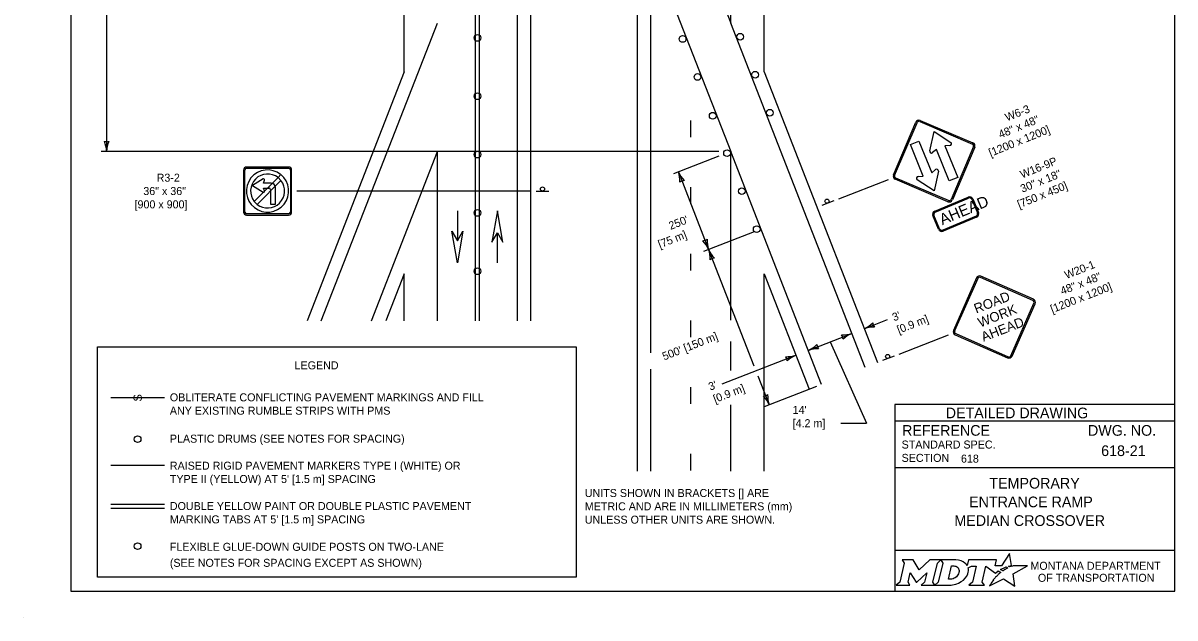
# Model space of a CAD drawing. Extents: x 49991.4 to 50021, y 49987.6 to 50011.4.
# Drawn here: x 49999.98 to 50008.61, y 49999.86 to 50004.32 of the extents above; entities that cross this region are included whole.
import ezdxf

# ---------------------------------------------------------------- set-up
doc = ezdxf.new("R2010")
doc.units = 0
for name, color, linetype in [('Level 1', 7, 'Continuous'), ('Level 2', 7, 'Continuous'), ('Level 3', 7, 'Continuous')]:
    doc.layers.add(name, color=color, linetype=linetype)

msp = doc.modelspace()

# ---------------------------------------------------------------- linework, layer by layer
at = {"layer": 'Level 1'}
for p, q in [((50005.2837, 50004.324), (50005.2837, 50010.8774)), ((50005.5337, 50003.9574), (50005.5337, 50010.8774)), ((50003.3688, 50002.0911), (50003.3688, 50010.5919)), ((50002.8337, 50003.9575), (50002.8337, 50010.5493)), ((50003.3988, 50002.0911), (50003.3988, 50010.5067)), ((50003.9712, 50007.6888), (50005.2838, 50004.3238)), ((50003.7838, 50002.0911), (50003.7838, 50006.931)), ((50003.6838, 50002.0911), (50003.6838, 50006.593)), ((50004.1009, 50006.393), (50005.2837, 50003.3608)), ((50004.5838, 50000.9624), (50004.5838, 50004.8798)), ((50004.6838, 50001.8518), (50004.6838, 50004.8987)), ((50002.2131, 50002.0911), (50003.0837, 50004.324)), ((50006.2908, 50001.741), (50005.2837, 50004.324)), ((50002.8337, 50003.9575), (50002.1063, 50002.0911)), ((50005.5337, 50003.9575), (50006.3835, 50001.7771)), ((50004.9838, 50003.469), (50004.9838, 50003.594)), ((50006.5034, 50003.1847), (50006.6713, 50003.5805)), ((50006.5127, 50003.1809), (50006.6806, 50003.5767)), ((50006.7003, 50003.5847), (50007.096, 50003.4168)), ((50006.7041, 50003.5938), (50007.1001, 50003.426)), ((50006.7761, 50003.3651), (50006.8088, 50003.5116)), ((50006.8088, 50003.5116), (50006.9339, 50003.4289)), ((50006.6315, 50003.4123), (50006.6945, 50003.4378)), ((50006.7273, 50003.1753), (50006.6315, 50003.4123)), ((50006.6945, 50003.4378), (50006.7903, 50003.2008)), ((50006.9277, 50003.4052), (50006.8896, 50003.4023)), ((50006.8896, 50003.4023), (50006.9853, 50003.1656)), ((50007.104, 50003.3971), (50006.9362, 50003.0011)), ((50002.5887, 50002.0911), (50003.0837, 50003.3608)), ((50003.0837, 50002.0911), (50003.0837, 50003.3608)), ((50005.9648, 50001.6138), (50005.2837, 50003.3608)), ((50005.2837, 50002.096), (50005.2837, 50003.3607)), ((50006.8266, 50003.3768), (50006.7972, 50003.3525)), ((50006.9223, 50003.1401), (50006.8266, 50003.3768)), ((50007.1134, 50003.3931), (50006.9453, 50002.9973)), ((50001.9681, 50003.2442), (50001.6531, 50003.2442)), ((50001.6531, 50003.2349), (50001.9681, 50003.2349)), ((50006.7903, 50003.2008), (50006.8195, 50003.2256)), ((50001.6307, 50003.2217), (50001.6307, 50002.9067)), ((50001.6401, 50002.9067), (50001.6401, 50003.2217)), ((50001.7763, 50003.1547), (50001.6981, 50003.1055)), ((50001.7105, 50002.9853), (50001.8895, 50003.1644)), ((50001.9107, 50003.1432), (50001.7317, 50002.9641)), ((50001.7763, 50003.1547), (50001.7763, 50003.1547)), ((50001.7803, 50003.1242), (50001.7873, 50003.1462)), ((50001.8891, 50003.1648), (50001.9085, 50003.1881)), ((50001.9091, 50003.1877), (50001.8895, 50003.1644)), ((50001.8895, 50003.1644), (50001.9107, 50003.1432)), ((50001.8895, 50003.1644), (50001.9107, 50003.1432)), ((50001.9907, 50003.2217), (50001.9813, 50003.2217)), ((50001.9813, 50003.2217), (50001.9907, 50003.2217)), ((50001.9907, 50003.2216), (50001.9813, 50003.2216)), ((50001.9813, 50003.2216), (50001.9813, 50002.9067)), ((50001.9907, 50002.9067), (50001.9907, 50003.2216)), ((50006.9125, 50002.984), (50006.5167, 50003.1519)), ((50006.9165, 50002.9932), (50006.5207, 50003.1613)), ((50006.808, 50003.0663), (50006.6826, 50003.1491)), ((50006.689, 50003.1728), (50006.7273, 50003.1753)), ((50006.8406, 50003.213), (50006.808, 50003.0663)), ((50006.9853, 50003.1656), (50006.9223, 50003.1401)), ((50001.6981, 50003.1055), (50001.7763, 50003.0562)), ((50001.8367, 50003.1242), (50001.7803, 50003.1242)), ((50001.7873, 50003.0648), (50001.7803, 50003.0867)), ((50001.7803, 50003.0867), (50001.8205, 50003.0867)), ((50001.8331, 50003.074), (50001.8331, 50002.9667)), ((50001.8707, 50002.9667), (50001.8707, 50003.0902)), ((50003.8238, 50003.0642), (50003.9198, 50003.0642)), ((50004.9838, 50002.969), (50004.9838, 50003.094)), ((50001.7317, 50002.9641), (50001.7105, 50002.9853)), ((50001.7317, 50002.9641), (50001.7105, 50002.9853)), ((50001.8331, 50002.9667), (50001.8707, 50002.9667)), ((50006.0562, 50002.9914), (50005.9667, 50002.9566)), ((50006.8131, 50002.9142), (50007.0642, 50003.0193)), ((50006.8163, 50002.9064), (50007.0674, 50003.0116)), ((50007.0905, 50003.0021), (50007.1333, 50002.8998)), ((50007.0983, 50003.0053), (50007.1411, 50002.9031)), ((50001.9681, 50002.8936), (50001.6531, 50002.8936)), ((50001.6531, 50002.8842), (50001.9681, 50002.8842)), ((50003.2337, 50002.9159), (50003.2337, 50002.6901)), ((50003.2339, 50002.9159), (50003.2339, 50002.6901)), ((50006.842, 50002.7778), (50006.7991, 50002.8801)), ((50006.8497, 50002.7811), (50006.8069, 50002.8834)), ((50006.8131, 50002.9142), (50006.8131, 50002.9142)), ((50006.8163, 50002.9064), (50006.8163, 50002.9064)), ((50007.1239, 50002.8767), (50006.8728, 50002.7716)), ((50007.1271, 50002.869), (50006.876, 50002.7639)), ((50003.5336, 50002.5259), (50003.5336, 50002.7517)), ((50003.5338, 50002.5259), (50003.5338, 50002.7517)), ((50004.9838, 50002.469), (50004.9838, 50002.594)), ((50002.8337, 50002.4442), (50002.6961, 50002.0911)), ((50002.8337, 50002.0911), (50002.8337, 50002.4442)), ((50005.5337, 50002.4442), (50005.8715, 50001.5774)), ((50005.5337, 50001.5963), (50005.5337, 50002.4442)), ((50007.1266, 50002.4121), (50006.9536, 50002.0185)), ((50007.1358, 50002.4084), (50006.9626, 50002.0147)), ((50007.5492, 50002.2428), (50007.1556, 50002.4162)), ((50007.5531, 50002.252), (50007.1597, 50002.4251)), ((50007.3839, 50001.8294), (50007.5568, 50002.223)), ((50007.3929, 50001.8255), (50007.566, 50002.219)), ((50004.9838, 50001.969), (50004.9838, 50002.094)), ((50005.2837, 50001.7181), (50005.2837, 50001.9348)), ((50006.9663, 50001.9858), (50007.3599, 50001.8125)), ((50006.9704, 50001.9949), (50007.3639, 50001.8217)), ((50000.5356, 50000.1675), (50000.5356, 50001.8961)), ((50000.5356, 50001.8961), (50004.124, 50001.8961)), ((50004.124, 50001.8961), (50004.124, 50000.1675)), ((50006.5099, 50001.8268), (50006.4204, 50001.7921)), ((50004.6838, 50000.9624), (50004.6838, 50001.7274)), ((50004.9838, 50001.469), (50004.9838, 50001.594)), ((50005.5337, 50000.9624), (50005.5337, 50001.5963)), ((50001.0367, 50001.5139), (50000.6356, 50001.5139)), ((50005.2837, 50000.9624), (50005.2837, 50001.4605)), ((50004.9838, 50000.969), (50004.9838, 50001.094)), ((50001.0367, 50001.0057), (50000.6356, 50001.0057)), ((50000.6356, 50000.7154), (50001.0367, 50000.7154)), ((50000.6356, 50000.6854), (50001.0367, 50000.6854)), ((50004.124, 50000.1675), (50000.5356, 50000.1675)), ((49999.9766, 49999.8624), (49999.9766, 49999.8624))]:
    msp.add_line(p, q, dxfattribs=at)
for points in [[(50008.6146, 50011.2628), (50000.3356, 50011.2628), (50000.3356, 50000.0624), (50008.6146, 50000.0624)], [(50003.5756, 50002.6795), (50003.5338, 50002.9159), (50003.492, 50002.6795), (50003.5338, 50002.7515)], [(50003.2757, 50002.7623), (50003.2339, 50002.5259), (50003.1921, 50002.7623), (50003.2339, 50002.6903)]]:
    msp.add_lwpolyline(points, close=True, dxfattribs=at)
for centre, radius in [((50003.3838, 50004.2123), 0.025), ((50004.9229, 50004.2044), 0.025), ((50005.3546, 50004.2214), 0.025), ((50005.034, 50003.9194), 0.025), ((50005.4658, 50003.9364), 0.025), ((50003.3838, 50003.7748), 0.025), ((50005.577, 50003.6514), 0.025), ((50005.148, 50003.629), 0.025), ((50003.3838, 50003.3373), 0.025), ((50005.2556, 50003.3479), 0.025), ((50003.8717, 50003.0794), 0.0152), ((50005.3668, 50003.0629), 0.025), ((50006.0055, 50002.9882), 0.0152), ((50003.3838, 50002.8998), 0.025), ((50005.478, 50002.7779), 0.025), ((50003.3838, 50002.4623), 0.025), ((50006.4596, 50001.8236), 0.0152), ((50000.836, 50001.2037), 0.025), ((50000.8361, 50000.401), 0.025)]:
    msp.add_circle(centre, radius, dxfattribs=at)
for centre, radius, start, end in [((50006.6942, 50003.5707), 0.025, 67.01358, 157.01358), ((50006.6942, 50003.5707), 0.015, 67.01358, 157.01358), ((50006.9266, 50003.4179), 0.0129, 274.05539, 345.29114), ((50006.9266, 50003.4179), 0.0129, 345.29419, 56.53298), ((50007.0901, 50003.4028), 0.015, 337.01358, 67.01358), ((50007.0901, 50003.4028), 0.025, 337.01358, 67.01358), ((50006.7886, 50003.3621), 0.0129, 167.59853, 238.72992), ((50006.7886, 50003.3621), 0.0129, 238.73297, 309.97176), ((50001.6531, 50003.2218), 0.0225, 90, 180), ((50001.6531, 50003.2218), 0.0131, 90, 180), ((50001.9681, 50003.2218), 0.0225, 0, 90), ((50001.9681, 50003.2218), 0.0131, 0, 90), ((50006.8277, 50003.2156), 0.0129, 58.73297, 129.97176), ((50006.8277, 50003.2156), 0.0129, 347.59853, 58.72992), ((50001.8101, 50003.0639), 0.1585, 51.65928, 51.42697), ((50001.8106, 50003.0643), 0.1275, 52.04534, 218.24287), ((50001.8106, 50003.0643), 0.1275, 135.58365, 135.71312), ((50001.8106, 50003.0643), 0.1275, 231.75713, 38.2435), ((50001.7801, 50003.1485), 0.00742, 342.38136, 122.24299), ((50006.5263, 50003.1749), 0.025, 157.01334, 247.01358), ((50006.5263, 50003.1749), 0.015, 157.01334, 247.01358), ((50006.6897, 50003.1598), 0.0129, 165.29419, 236.53298), ((50006.6897, 50003.1598), 0.0129, 94.05539, 165.29114), ((50001.7801, 50003.0626), 0.00742, 237.75616, 17.61961), ((50001.8204, 50003.0741), 0.0128, 0, 90), ((50001.8366, 50003.0903), 0.034, 0, 90), ((50001.8106, 50003.0643), 0.1275, 319.12855, 319.14364), ((50006.9221, 50003.007), 0.025, 247.01401, 337.01358), ((50006.9221, 50003.007), 0.015, 247.01401, 337.01358), ((50007.0742, 50002.9953), 0.026, 22.71919, 112.71919), ((50007.0742, 50002.9953), 0.0176, 22.71919, 112.71919), ((50001.6531, 50002.9068), 0.0225, 180, 270), ((50001.6531, 50002.9068), 0.0131, 180, 270), ((50001.9681, 50002.9068), 0.0225, 270, 0), ((50001.9681, 50002.9068), 0.0131, 270, 0), ((50006.8232, 50002.8902), 0.026, 112.71919, 202.71919), ((50006.8232, 50002.8902), 0.0176, 112.71919, 202.71919), ((50007.1171, 50002.893), 0.0176, 292.71919, 22.71919), ((50007.1171, 50002.893), 0.026, 292.71919, 22.71919), ((50006.866, 50002.7879), 0.026, 202.71919, 292.71919), ((50006.866, 50002.7879), 0.0176, 202.71919, 292.71919), ((50007.1497, 50002.402), 0.025, 66.25, 156.25), ((50007.1497, 50002.402), 0.015, 66.25, 156.25), ((50007.5433, 50002.2289), 0.015, 336.25, 66.25024), ((50007.5433, 50002.2289), 0.025, 336.25, 66.25024), ((50006.9765, 50002.0085), 0.025, 156.25, 246.25), ((50006.9765, 50002.0085), 0.015, 156.25, 246.25), ((50007.3701, 50001.8353), 0.025, 246.25, 336.24957), ((50007.3701, 50001.8353), 0.015, 246.25, 336.24957)]:
    msp.add_arc(centre, radius, start, end, dxfattribs=at)
at = {"layer": 'Level 2'}
for p, q in [((50008.6146, 50001.4624), (50006.5146, 50001.4624)), ((50006.5146, 50001.4624), (50006.5146, 50000.0624)), ((50008.6146, 50001.3374), (50006.5146, 50001.3374)), ((50008.2507, 50001.1223), (50008.2507, 50001.1223)), ((50008.6146, 50000.9874), (50006.5146, 50000.9874)), ((50007.0089, 50001.0629), (50007.0089, 50001.0629)), ((50007.5646, 50000.7383), (50007.5646, 50000.7383)), ((50008.6146, 50000.3693), (50006.5146, 50000.3693))]:
    msp.add_line(p, q, dxfattribs=at)
for points in [[(50006.5701, 50000.2974), (50006.5842, 50000.274), (50006.5507, 50000.1307), (50006.525, 50000.1082), (50006.6266, 50000.1082), (50006.6131, 50000.131), (50006.6293, 50000.2011), (50006.673, 50000.1321), (50006.6783, 50000.1321), (50006.7534, 50000.2016), (50006.737, 50000.1305), (50006.7123, 50000.1085), (50006.8139, 50000.1085), (50006.8001, 50000.1318), (50006.8333, 50000.2742)], [(50006.8333, 50000.2742), (50006.8586, 50000.2974), (50006.7762, 50000.2974), (50006.6966, 50000.2244), (50006.6521, 50000.2971), (50006.5701, 50000.2974)], [(50006.9722, 50000.2974), (50006.8586, 50000.2974), (50006.8733, 50000.2745), (50006.8394, 50000.1307), (50006.8139, 50000.1085), (50006.9245, 50000.1085)], [(50007.3771, 50000.2447), (50007.3668, 50000.2503), (50007.3784, 50000.2531), (50007.39, 50000.2551), (50007.3726, 50000.3452), (50007.3131, 50000.2539), (50007.2658, 50000.2532), (50007.2761, 50000.2973), (50007.0669, 50000.2974), (50007.0568, 50000.2549), (50007.051, 50000.2632)], [(50006.9962, 50000.2107), (50006.995, 50000.2026), (50006.9918, 50000.1933), (50006.9876, 50000.1851), (50006.982, 50000.1776), (50006.9755, 50000.1707), (50006.9676, 50000.1644), (50006.9593, 50000.1597), (50006.9502, 50000.1558), (50006.9411, 50000.1535), (50006.9319, 50000.1526), (50006.916, 50000.1526), (50006.9396, 50000.2526), (50006.9556, 50000.2526), (50006.9632, 50000.252), (50006.9708, 50000.2501), (50006.9774, 50000.2471), (50006.9835, 50000.2429), (50006.9883, 50000.2379), (50006.992, 50000.2319), (50006.9947, 50000.2257), (50006.9963, 50000.2183), (50006.9963, 50000.2153), (50006.9962, 50000.2107)], [(50007.0636, 50000.2383), (50007.0882, 50000.2514), (50007.1251, 50000.2514), (50007.0965, 50000.1309), (50007.069, 50000.1082), (50007.1852, 50000.1082), (50007.1682, 50000.1311), (50007.1964, 50000.2513), (50007.2677, 50000.1996), (50007.2888, 50000.2147), (50007.3085, 50000.2038)], [(50007.2527, 50000.1479), (50007.2374, 50000.1235), (50007.2327, 50000.116), (50007.2269, 50000.1074), (50007.2246, 50000.1031), (50007.3299, 50000.1562), (50007.4138, 50000.1011), (50007.4007, 50000.1938), (50007.5076, 50000.2522), (50007.4583, 50000.253), (50007.4282, 50000.2534), (50007.4074, 50000.2537), (50007.4006, 50000.2522), (50007.3957, 50000.251), (50007.3873, 50000.2487), (50007.3771, 50000.2447)], [(50007.3267, 50000.2171), (50007.3243, 50000.2154), (50007.306, 50000.225), (50007.3163, 50000.2307), (50007.3204, 50000.2329), (50007.329, 50000.2369), (50007.3347, 50000.2395), (50007.3426, 50000.2425), (50007.3499, 50000.2452), (50007.3617, 50000.2378), (50007.3577, 50000.2357), (50007.3531, 50000.2332), (50007.3489, 50000.231), (50007.3439, 50000.2281), (50007.342, 50000.227), (50007.3393, 50000.2254), (50007.3368, 50000.224), (50007.3345, 50000.2224), (50007.3319, 50000.2206), (50007.3292, 50000.2188), (50007.3267, 50000.2171)], [(50006.9702, 50000.1158), (50006.9786, 50000.1184), (50006.9916, 50000.1238), (50007.012, 50000.1348)], [(50007.2666, 50000.164), (50007.2666, 50000.164)]]:
    msp.add_lwpolyline(points, dxfattribs=at)
for centre, radius, start, end in [((50006.9953, 50000.219), 0.0709, 339.53292, 15.85821), ((50006.9513, 50000.2363), 0.1183, 300.91025, 339.13831)]:
    msp.add_arc(centre, radius, start, end, dxfattribs=at)
for centre, major_axis, ratio, start_param, end_param in [((50006.9701, 50000.25), (0.0834, -0.0037), 0.568097, 0.61298, 1.570796), ((50007.0257, 50000.2573), (0.0361, -0.0295), 0.469099, 1.225588, 1.570796), ((50007.2974, 50000.1941), (-0.0112, -0.0097), 0.021651, 3.157348, 6.283185), ((50006.9248, 50000.2568), (0, 0.1484), 0.987302, 3.139398, 3.456847), ((50007.2597, 50000.1559), (-0.00694, -0.00806), 0.008222, 0, 3.137361), ((50007.2764, 50000.1742), (-0.0098, -0.0102), 0.016458, 3.141593, 6.279097)]:
    msp.add_ellipse(centre, major_axis=major_axis, ratio=ratio, start_param=start_param, end_param=end_param, dxfattribs=at)
at = {"layer": 'Level 3'}
for p, q in [((50000.6034, 50007.4623), (50000.6034, 50003.3608)), ((50005.1943, 50003.3608), (50000.5634, 50003.3608)), ((50005.1945, 50003.3259), (50004.8534, 50003.1929)), ((50004.8907, 50003.2075), (50005.1178, 50002.6252)), ((50006.0934, 50003.0061), (50006.4659, 50003.1509)), ((50003.7838, 50003.0642), (50002.0307, 50003.0642)), ((50005.4588, 50002.7593), (50005.0802, 50002.6116)), ((50005.1178, 50002.6252), (50005.4579, 50001.7535)), ((50006.2842, 50002.0319), (50006.4596, 50002.1001)), ((50005.8653, 50001.869), (50006.1915, 50001.9958)), ((50006.0284, 50001.9324), (50006.3019, 50001.3228)), ((50006.5471, 50001.8414), (50006.916, 50001.9848)), ((50005.2199, 50001.618), (50005.772, 50001.8327)), ((50005.4869, 50001.6789), (50005.5721, 50001.4606)), ((50005.9275, 50001.5993), (50005.5348, 50001.4461)), ((50006.1089, 50001.3228), (50006.3019, 50001.3228))]:
    msp.add_line(p, q, dxfattribs=at)
for centre, radius, start, end in [((50000.6034, 50003.489), 0.0548, 252.13882, 287.86118), ((50000.3707, 50003.3493), 0.233, 2.82731, 22.07716), ((50000.8256, 50003.3516), 0.2223, 157.45601, 177.63952), ((50004.6804, 50003.1353), 0.2223, 358.76551, 18.94902), ((50005.1033, 50003.3027), 0.233, 204.13681, 223.38666), ((50004.9373, 50003.088), 0.0548, 93.44832, 129.17068), ((50005.0709, 50002.7456), 0.0548, 273.44832, 309.17068), ((50004.9049, 50002.5308), 0.233, 24.13681, 43.38666), ((50005.3278, 50002.6983), 0.2223, 178.76551, 198.94902), ((50004.9072, 50002.5539), 0.2223, 358.76551, 18.94902), ((50005.3301, 50002.7214), 0.233, 204.13681, 223.38666), ((50005.1641, 50002.5067), 0.0548, 93.44832, 129.17068), ((50006.1889, 50002.2445), 0.233, 294.13681, 313.38666), ((50006.3564, 50001.8216), 0.2223, 88.76551, 108.94902), ((50006.4036, 50002.0785), 0.0548, 183.44832, 219.17068), ((50006.1209, 50002.2179), 0.233, 268.36713, 287.61698), ((50006.0713, 50001.951), 0.0548, 2.58311, 38.30547), ((50006.2776, 50001.7909), 0.2223, 112.80477, 132.98828), ((50005.77, 50002.0816), 0.233, 294.13681, 313.38666), ((50005.9375, 50001.6587), 0.2223, 88.76551, 108.94902), ((50005.9847, 50001.9156), 0.0548, 183.44832, 219.17068), ((50005.7015, 50002.0548), 0.233, 268.36713, 287.61698), ((50005.6519, 50001.7879), 0.0548, 2.58311, 38.30547), ((50005.8582, 50001.6278), 0.2223, 112.80477, 132.98828), ((50005.5255, 50001.5801), 0.0548, 273.44832, 309.17068), ((50005.3595, 50001.3654), 0.233, 24.13681, 43.38666), ((50005.7824, 50001.5328), 0.2223, 178.76551, 198.94902)]:
    msp.add_arc(centre, radius, start, end, dxfattribs=at)

# ---------------------------------------------------------------- texts
at = {"layer": 'Level 1'}
for s, height, rotation, p in [('AHEAD', 0.084, 22.71919, (50006.8696, 50002.8069)), ('ROAD', 0.0725, 21.25, (50007.1245, 50002.1449)), ('WORK', 0.0725, 21.25, (50007.1544, 50002.0402)), ('AHEAD', 0.0725, 21.25, (50007.1789, 50001.9329)), ('S', 0.0625, 90, (50000.8674, 50001.485))]:
    msp.add_text(s, height=height, rotation=rotation, dxfattribs=at).set_placement(p)
at = {"layer": 'Level 2'}
for s, rotation, p in [('W6-3', 22.01358, (50007.3551, 50003.5856)), ('48" x 48"', 22.01358, (50007.3056, 50003.4578)), ('[1200 x 1200]', 22.01358, (50007.2324, 50003.3203)), ('W16-9P', 22.01358, (50007.4682, 50003.1577)), ('30" x 18"', 22.01358, (50007.4702, 50003.0507)), ('[750 x 450]', 22.01358, (50007.4469, 50002.9334)), ("250'", 21.3095, (50004.8322, 50002.772)), ('[75 m]', 21.3095, (50004.7521, 50002.6334)), ('W20-1', 21.25, (50007.8006, 50002.4038)), ('48" x 48"', 21.25, (50007.7694, 50002.2844)), ('[1200 x 1200]', 21.25, (50007.6944, 50002.1479)), ("3'", 21.3095, (50006.5079, 50002.0864)), ('[0.9 m]', 21.3095, (50006.5442, 50001.9932)), ("500' [150 m]", 21.3095, (50004.7841, 50001.793)), ("3'", 21.3095, (50005.1302, 50001.5664)), ('[0.9 m]', 21.3095, (50005.1665, 50001.4733)), ("14'", 0, (50005.7475, 50001.3928)), ('[4.2 m]', 0, (50005.7475, 50001.2928))]:
    msp.add_text(s, height=0.06, rotation=rotation, dxfattribs=at).set_placement(p)
for s, height, p in [('R3-2', 0.06, (50000.9785, 50003.1342)), ('36" x 36"', 0.06, (50000.8784, 50003.0342)), ('[900 x 900]', 0.06, (50000.8128, 50002.9342)), ('LEGEND', 0.06, (50002.0127, 50001.7269)), ('OBLITERATE CONFLICTING PAVEMENT MARKINGS AND FILL ', 0.06, (50001.0775, 50001.487)), ('ANY EXISTING RUMBLE STRIPS WITH PMS', 0.06, (50001.0775, 50001.387)), ('DETAILED DRAWING', 0.0799, (50006.8956, 50001.3599)), ('PLASTIC DRUMS (SEE NOTES FOR SPACING)', 0.06, (50001.0775, 50001.1769)), ('REFERENCE', 0.08, (50006.5682, 50001.229)), ('DWG. NO.', 0.08, (50007.9624, 50001.229)), ('STANDARD SPEC.', 0.06, (50006.5649, 50001.133)), ('618-21', 0.08, (50008.0613, 50001.0767)), ('SECTION', 0.06, (50006.5649, 50001.033)), ('618', 0.06, (50007.01, 50001.0273)), ('RAISED RIGID PAVEMENT MARKERS TYPE I (WHITE) OR ', 0.06, (50001.0775, 50000.9744)), ("TYPE II (YELLOW) AT 5' [1.5 m] SPACING", 0.06, (50001.0775, 50000.8744)), ('TEMPORARY', 0.08, (50007.223, 50000.8327)), ('UNITS SHOWN IN BRACKETS [] ARE ', 0.06, (50004.1891, 50000.7696)), ('DOUBLE YELLOW PAINT OR DOUBLE PLASTIC PAVEMENT', 0.06, (50001.0775, 50000.6718)), ('METRIC AND ARE IN MILLIMETERS (mm) ', 0.06, (50004.1891, 50000.6696)), ('ENTRANCE RAMP', 0.08, (50007.0711, 50000.6927)), ("MARKING TABS AT 5' [1.5 m] SPACING", 0.06, (50001.0775, 50000.5718)), ('MEDIAN CROSSOVER', 0.08, (50006.9605, 50000.5527)), ('UNLESS OTHER UNITS ARE SHOWN.', 0.06, (50004.1891, 50000.5696)), ('FLEXIBLE GLUE-DOWN GUIDE POSTS ON TWO-LANE', 0.06, (50001.0775, 50000.366)), ('(SEE NOTES FOR SPACING EXCEPT AS SHOWN)', 0.06, (50001.0775, 50000.246)), ('MONTANA DEPARTMENT', 0.06, (50007.5308, 50000.2236)), ('OF TRANSPORTATION', 0.06, (50007.587, 50000.1336))]:
    msp.add_text(s, height=height, dxfattribs=at).set_placement(p)

doc.saveas('drawing.dxf')
